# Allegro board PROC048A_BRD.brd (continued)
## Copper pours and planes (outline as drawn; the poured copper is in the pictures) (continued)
1V1 on TOP: 73.25,59.99 75.28,59.99 75.41,60.12 76.04,60.12 76.42,59.74 76.42,58.85 76.04,58.85 75.53,59.36 73.25,59.36 73.12,59.48 73.12,59.86
1V1 on TOP: 48.94,56.86 48.94,55.07 49.14,54.88 50.68,54.88 51.1,55.29 54.45,55.29 54.7,55.55 54.7,57.45 54.58,57.58 53.18,57.58 53.05,57.45 51.66,57.45 51.22,57.01 49.09,57.01
1V1 on BOTTOM: 72.38,63.53 72.61,63.29 72.61,61.9 72.93,61.57 74.19,61.57 74.39,61.77 76.42,61.77 76.55,61.64 76.55,58.97 76.42,58.85 75.66,58.85 75.53,58.97 75.53,59.23 75.41,59.36 73.39,59.36 72.43,58.39 72.43,53.21 70.57,51.35 60.55,51.35 59.53,52.37 59.53,57.32 59.4,57.45 56.48,57.45 56.23,57.2 56.23,56.18 55.85,55.8 49.75,55.8 49.24,56.31 49.24,67.73 50.31,68.79 63.59,68.79 63.92,68.47 63.92,65.13 65.52,63.53 ; 1 cut-out
1V35 on TOP: 36.42,66.59 36.42,63.8 36.16,63.55 32.48,63.55 32.29,63.74 32.29,66.53 32.48,66.72 36.29,66.72
1V35 on BOTTOM: 93.57,36.11 93.57,34.51 93.46,34.4 93.46,32.2 92.24,30.98 86.76,30.98 86.45,30.67 86.45,27.42 86.84,27.03 93.6,27.03 93.97,26.66 95.32,26.66 95.4,26.74 95.4,30.83 95.39,30.84 95.39,31.56 95.09,31.86 95.09,34.72 94.84,34.97 94.33,34.97 94.07,35.23 94.07,36.11 93.95,36.24 93.69,36.24
1V35 on L05_PWR1: 47.08,31.29 47.08,36.5 48.12,37.53 48.12,45.04 46.82,46.33 33.59,46.33 32.61,47.31 32.61,53.85 30.97,55.49 30.97,67.86 31.73,68.62 47.97,68.62 53.61,74.26 99.55,74.26 100.81,73 100.81,42.7 100.98,42.52 100.98,24.96 100.12,24.1 49.62,24.1 48.48,25.24 48.48,28.99 47.1,30.37 47.1,31.27
2V5 on TOP: 52.19,66.62 55.89,66.62 56.1,66.84 56.1,68.85 55.94,69.01 50.26,69.01 49.88,68.63 49.88,64.94 50,64.82 51.37,64.82 51.48,64.92 51.48,65.91
2V5 on TOP: 74.39,61.01 73.5,61.01 73.5,61.9 73.25,62.15 73.25,62.28 74.14,63.17 74.26,63.17 74.39,63.04
2V5 on TOP: 73.25,54.15 73.25,57.07 74.39,57.07 74.39,54.66 74.64,54.4 74.64,54.15 74.52,54.02 73.37,54.02
2V5 on BOTTOM: 30.88,50.92 34.36,50.92 34.77,51.33 34.74,53.51 34.45,53.8 30.92,53.8 30.68,53.56 30.68,51.13
2V5 on BOTTOM: 73.05,53.66 74.33,53.66 74.5,53.82 74.5,54.47 74.22,54.74 74.22,56.13 74.09,56.27 73.13,56.27 72.94,56.08 72.94,53.77
2V5 on L03_SIG1: 48.86,63.8 48.86,72 49.56,72.69 74.03,72.69 74.88,71.84 74.88,53.74 74.33,53.19 63.9,53.19 63.34,53.75 63.34,62.61 62.84,63.11 49.55,63.11
2V5 on L06_PWR2: 49.96,68.31 49.96,65.03 50.36,64.63 63.41,64.63 63.98,65.2 63.98,80.56 63.34,81.2 18.76,81.2 17.56,79.99 17.56,43.04 17.87,42.72 29.94,42.72 30.7,41.96 30.7,35.99 31.72,34.97 40.48,34.97 40.73,35.23 40.73,37.26 39.97,38.02 39.97,50.47 34.38,56.05 34.38,67.99 35.75,69.35 48.91,69.35
2V5_A on TOP (solid shape): 62.11,75.1 62.11,73.15 61.88,72.92 60.29,72.92 60.04,72.66 60.04,67.19 59.66,66.81 57.01,66.81 56.8,67.01 56.8,74.91 57.12,75.23 61.98,75.23
3V3 on TOP (solid shape): 91.45,24.66 91.39,24.5 91.23,24.44 90.11,24.62 90.23,25.66 91.27,25.78
3V3 on TOP: 46.83,63.55 43.02,63.55 42.89,63.67 42.89,66.47 43.15,66.72 46.83,66.72 47.08,66.47 47.08,63.8
3V3 on TOP: 82.39,10.59 82.64,10.33 83.53,10.33 83.66,10.46 83.66,11.6 83.53,11.73 82.64,11.73
3V3 on TOP: 89.69,81.3 89.69,79.99 89.86,79.82 91,79.82 91.19,80.01 91.19,81.27 91,81.47 89.85,81.47
3V3 on TOP: 90.06,83.76 91.08,83.76 91.27,83.94 91.27,85.25 91.1,85.42 90.06,85.42 89.87,85.23 89.87,83.95
3V3 on BOTTOM: 4.57,69.81 4.57,71.26 4.84,71.53 14.77,71.53 15,71.3 15,69.69 14.88,69.57 4.81,69.57
3V3 on BOTTOM: 2.28,91.84 2.13,91.99 2.13,93.01 2.28,93.16 19.28,93.16 19.28,93.17 20,93.17 20.12,93.05 20.12,92 19.96,91.84
3V3 on BOTTOM: 31.46,15.4 31.46,16.05 31.21,16.3 27.27,16.3 27.15,16.43 27.15,17.45 27.27,17.57 32.23,17.57 32.5,17.3 32.5,15.43 32.4,15.33 31.53,15.33
3V3 on L06_PWR2: 1.02,6.02 1.02,93.98 99.3,93.98 100.98,92.3 100.98,6.02
3V3_A on TOP (solid shape): 49.5,74.98 49.5,73.07 49.24,72.82 48.48,72.82 48.23,72.56 48.23,69.11 47.74,68.63 47.73,68.63 46.33,67.23 44.54,67.23 44.35,67.42 44.35,75.04 44.54,75.23 49.24,75.23
5V on TOP (solid shape): 54.58,83.36 54.58,82.95 54.48,82.77 54.45,82.58 54.45,81.1 54.58,80.97 54.58,80.18 55.06,79.7 55.89,79.7 56.23,79.36 56.23,74.29 56.13,74.19 53.36,74.19 53.05,74.5 53.05,79.93 52.42,80.56 52.42,81.18 52.42,81.18 52.42,82.58 52.39,82.77 52.29,82.95 52.29,83.36 52.42,83.49 54.45,83.49
5V on TOP (solid shape): 29.81,83.36 29.81,82.95 29.72,82.77 29.69,82.58 29.69,81.1 29.81,80.97 29.81,80.18 30.32,79.68 31.18,79.68 31.46,79.39 31.46,74.56 31.33,74.43 28.46,74.43 28.42,74.48 28.42,79.89 28.2,80.11 28.2,80.12 28.18,80.12 27.65,80.65 27.65,81.18 27.65,82.58 27.62,82.77 27.53,82.95 27.53,83.36 27.65,83.49 29.69,83.49
5V on BOTTOM: 46.63,57.38 47.72,58.47 47.72,68.2 48.91,69.39 56.36,69.39 57.5,70.53 57.5,92.88 56.61,93.77 38.07,93.77 37.81,93.52 37.81,92.38 37.43,91.99 35.27,91.99 34.89,92.38 34.89,93.65 34.77,93.77 25.62,93.77 24.61,92.76 24.61,90.22 24.1,89.71 19.04,89.71 18.45,89.11 18.45,58.2 19.27,57.38
GND on TOP (solid shape): 52.55,79.68 52.55,74.21 53.18,73.58 55.09,73.58 55.21,73.45 55.21,69.9 54.9,69.58 50.58,69.58 50.25,69.9 50.25,77.43 50.26,77.43 50.26,79.55 50.49,79.77 52.45,79.77
GND on TOP (solid shape): 27.91,79.68 27.91,74.21 28.11,74.01 28.17,74.01 28.25,73.92 30.23,73.92 30.32,73.83 30.32,69.77 29.94,69.39 26.26,69.39 26.25,69.39 25.77,69.39 25.49,69.66 25.49,77.5 25.5,77.5 25.5,79.55 25.8,79.86 27.12,79.86 27.13,79.87 27.72,79.87
GND on TOP: 10.93,35.65 10.93,37.59 11.06,37.72 11.88,37.72 12.04,37.88 12.04,39.41 11.91,39.54 9.62,39.54 9.39,39.31 9.39,35.64 9.59,35.44 10.72,35.44
GND on TOP: 79.6,11.73 80.23,11.73 80.61,11.35 81.76,11.35 81.88,11.22 81.88,9.7 81.76,9.57 79.72,9.57 79.47,9.83 79.47,11.6
GND on TOP: 17.39,68.62 15.85,68.62 15.69,68.78 15.69,73.72 15.86,73.89 17.46,73.89 17.76,73.59 17.76,68.99
GND on TOP: 94.9,75.68 94.71,75.48 93.95,75.48 93.57,75.87 93.57,76.88 93.82,77.14 94.71,77.14 94.9,76.94
GND on TOP: 62.89,73.12 62.32,72.56 62.32,69.9 62.07,69.64 60.95,69.64 60.79,69.49 60.79,68.33 60.88,68.25 67.73,68.25 68.42,68.94 68.42,70.51 68.14,70.79 65.1,70.79 64.84,71.04 64.84,72.9 64.62,73.12
GND on TOP: 95.22,28.49 95.22,27.1 95.09,26.97 94.07,26.97 93.95,27.1 93.95,28.49 94.07,28.62 95.09,28.62
GND on TOP: 54.67,54.82 54.88,54.62 54.88,54.09 53.38,52.59 50.8,52.59 50.69,52.7 50.69,54.15 51.15,54.61 53.42,54.61 53.63,54.82
GND on TOP: 25.63,39.16 25.52,39.26 25.05,39.26 24.98,39.2 24.98,35.61 25.12,35.48 25.37,35.48 25.63,35.74
GND on TOP: 47.79,67.68 48.8,67.68 49.12,67.36 49.12,64.56 49.38,64.3 53.32,64.3 53.56,64.05 53.56,62.96 53.4,62.8 49.09,62.8 48.1,61.81 48.1,60.24 47.97,60.12 46.07,60.12 45.81,59.86 45.81,57.97 45.69,57.84 41.99,57.84 41.52,58.31 41.52,62.66 41.89,63.04 47.08,63.04 47.59,63.56 47.59,67.48
GND on TOP: 38.07,74.09 38.07,68.88 38.19,68.75 42,68.75 42.13,68.88 42.13,74.09 42,74.21 38.19,74.21
GND on BOTTOM: 70.07,48.04 79.66,48.04 79.81,48.18 79.81,49.18 79.71,49.27 70.05,49.27 69.94,49.16 69.94,48.17
GND on BOTTOM: 87.51,33.53 87.97,33.53 88.15,33.35 92.45,33.35 92.58,33.23 92.58,32.05 92.31,31.78 87.39,31.78 87.28,31.89 87.28,33.31
GND on BOTTOM: 65.95,26.97 68.23,26.97 68.41,26.8 71.37,26.8 71.51,26.65 71.51,24.2 71.13,23.82 66.25,23.82 65.81,24.27 65.81,26.83
GND on BOTTOM: 25.37,78.79 26.64,78.79 26.89,78.53 26.89,76.75 27.65,75.99 27.65,75.61 27.4,75.36 25.37,75.36 24.99,75.74 24.99,78.41
GND on BOTTOM: 23.08,40.81 26.38,44.12 26.38,50.21 25,51.6 25,54.79 25.25,55.04 29.94,55.04 30.17,54.81 30.17,48.96 31.14,47.99 31.14,46.37 31.04,46.27 30.45,46.27 30.19,46.02 30.19,43.61 30.7,43.1 30.7,41.83 29.18,40.31 28.03,40.31 24.1,36.37 10.05,36.37 9.62,36.8 9.62,39.92 10.51,40.81
GND on BOTTOM: 42,41.19 42.39,41.19 43.78,39.8 43.78,39.04 43.66,38.91 43.02,38.91 43.02,38.65 42.64,38.27 42,38.27 41.88,38.15 41.88,37.77 42,37.64 42.77,37.64 42.77,37 42.64,36.88 39.21,36.88 39.18,36.85 37.66,36.85 37.58,36.93 37.58,37.28 37.72,37.42 38.19,37.42 38.3,37.53 38.3,38.23 38.39,38.32 38.83,38.32 38.87,38.28 38.87,37.55 38.94,37.48 39.9,37.48 39.97,37.56 39.97,38.65 39.21,39.42 39.21,45.13 39.72,45.64 41.24,45.64 41.37,45.51 41.37,42.59 41.62,42.34 41.62,41.58
GND on BOTTOM: 37.5,22.06 37.36,22.2 37.36,23.33 37.44,23.4 39.19,23.4 39.43,23.16 41.37,23.16 41.66,23.46 42.23,23.46 42.35,23.46 42.43,23.37 42.43,22.28 42.21,22.06
GND on BOTTOM: 61.36,89.95 61.01,90.3 61.01,93.1 61.25,93.34 63.27,93.34 63.53,93.07 63.53,90.3 63.19,89.95
GND on BOTTOM: 86.1,35.89 86.47,36.26 86.47,40.8 86.33,40.95 85.5,40.95 85.41,40.86 85.41,35.92 85.45,35.89
GND on BOTTOM: 95.6,32.08 95.6,34.72 98.01,34.72 98.46,35.17 98.46,37.24 98.32,37.38 95.6,37.38 95.34,37.13 95.34,37 94.93,36.59 91.49,36.59 91.28,36.8 91.28,38.02 91.37,38.1 94.7,38.1 94.97,38.38 94.97,39.16 95.42,39.61 100.37,39.61 100.73,39.25 100.73,32.15 100.31,31.73 95.95,31.73
GND on BOTTOM: 35.02,34.59 35.91,34.59 36.16,34.34 36.16,33.96 36.29,33.83 37.56,33.83 37.81,33.57 38.19,33.57 38.32,33.7 38.32,33.96 38.83,34.46 40.23,34.46 40.36,34.6 40.36,35.86 40.23,35.99 39.85,35.99 39.72,35.86 39.72,35.73 39.59,35.73 39.46,35.61 39.08,35.61 38.96,35.73 37.05,35.73 36.92,35.86 36.92,36.62 36.54,36.62 36.01,36.09 35.25,36.09 34.64,35.48 34.64,34.97 34.33,34.66 33.56,34.66 33.5,34.72 33.5,36.11 33.37,36.24 32.61,36.24 31.59,35.23 31.59,33.83 32.23,33.19 34.51,33.19 34.77,33.45 34.77,34.34
GND on BOTTOM: 84.16,32.59 84.26,32.49 84.26,30.99 84.01,30.73 82.34,30.73 82.18,30.58 80.34,30.58 80.09,30.83 80.09,32.47 80.21,32.59
GND on BOTTOM: 50.01,78.66 51.4,78.66 51.53,78.53 51.53,76.88 52.55,75.87 52.55,75.36 52.42,75.23 50.01,75.23 49.75,75.48 49.75,78.41
GND on L02_GND1, L07_GND3: 1.02,6.02 1.02,93.98 100.98,93.98 100.98,6.02
GND on L04_GND2: 1.02,6.02 1.02,93.98 100.98,93.98 100.98,6.02
GND on L05_PWR1: 1.02,76.88 1.02,93.98 100.98,93.98 100.98,75.48 53.43,75.48 47.59,69.64 34.77,69.64 28.8,75.61 2.29,75.61 ; 1 cut-out
GND on L05_PWR1: 1.02,6.02 1.02,23.03 100.98,23.03 100.98,6.02
GND on L09_GND4: 1.02,6.02 1.02,93.98 100.98,93.98 100.98,6.02
GND_EARTH on TOP: 90.52,68.12 91.28,68.12 91.66,67.74 94.84,67.74 94.96,67.61 94.96,66.34 94.84,66.21 90.52,66.21 90.26,66.47 90.26,67.86
GND_SDCD on BOTTOM: 64.18,93.79 64.38,93.98 67.96,93.98 68.23,93.72 68.23,90.97 67.8,90.55 64.54,90.55 64.18,90.9
GND_SDCD on L03_SIG1: 66.01,93.9 85.05,93.9 85.54,93.41 85.54,77.21 84.86,76.54 66.89,76.54 65.65,77.77 65.65,93.54
VCC5V_CONN on TOP: 20.92,35.1 20.92,35.99 21.81,36.88 21.81,37.94 20.89,38.86 18.04,38.86 17.01,37.84 17.01,36.02 16.48,35.48 14.7,35.48 14.57,35.35 12.67,35.35 12.54,35.48 12.54,39.8 12.29,40.05 7.97,40.05 6.57,41.45 1.69,41.45 1.02,42.12 1.02,51.01 1.88,51.86 6.31,51.86 7.22,50.95 7.22,47.68 9.26,45.64 23.84,45.64 24.48,45 24.48,35.61 24.35,35.48 23.72,35.48 23.21,34.97 21.05,34.97
VCC5V_EXT on TOP: 22.4,46.99 22.92,47.51 22.92,60.91 22.32,61.51 10.38,61.51 7.08,58.21 7.08,53.26 8.21,52.13 9.78,52.13 11.09,50.82 11.09,47.37 11.48,46.99
VCC_1V1 on TOP (solid shape): 24.93,75.29 24.93,73.14 24.35,72.56 24.35,67.74 23.97,67.36 20.29,67.36 19.91,67.74 19.91,75.36 20.03,75.48 24.73,75.48
VCC_AUX on BOTTOM: 35.23,49.45 35.23,44.1 34.69,43.56 31.04,43.56 30.73,43.87 30.73,45.6 30.81,45.67 31.7,45.67 31.82,45.79 31.82,48.4 31.31,48.9 31.31,49.7 31.58,49.97 34.71,49.97
VCC_AUX on L08_SIG2: 41.24,37.64 45.2,37.64 46.88,39.32 46.88,39.89 47.37,40.38 48.78,40.38 49.39,39.78 49.39,39.46 48.94,39 48.94,38.19 47.97,37.22 47.97,36.86 47.66,36.55 47.66,34.11 47.97,33.8 47.97,27.75 48.68,27.04 50.04,27.04 50.39,26.7 50.39,25.57 49.88,25.07 41.75,25.07 41.24,25.57 41.24,29.38 40.86,29.76 39.34,29.76 38.96,30.15 38.96,31.54 38.32,31.54 37.31,32.56 34.51,32.56 31.97,35.1 29.18,35.1 27.53,36.75 27.53,43.73 28.67,44.88 29.87,44.88 30.7,45.7 36.04,45.7 39.24,42.5 39.24,39.64
VCC_CORE on TOP: 24.61,66.47 24.61,63.8 24.35,63.55 20.67,63.55 20.41,63.8 20.41,66.47 20.67,66.72 24.35,66.72
VCC_CORE on BOTTOM: 40.86,36.24 40.86,34.35 40.67,34.16 40.32,34.16 40.32,33.5 40.48,33.33 40.48,32.94 39.59,32.05 39.21,32.05 39.08,32.18 39.08,32.56 38.83,32.81 37.81,32.81 37.31,33.32 36.67,33.32 36.42,33.07 36.42,32.18 36.8,31.8 36.8,30.27 36.92,30.15 37.56,30.15 37.81,29.89 38.45,29.89 38.96,30.4 38.96,30.65 39.21,30.91 45.69,30.91 46.07,31.29 46.07,33.07 46.32,33.32 46.32,34.59 46.07,34.84 46.07,36.5 45.94,36.62 41.24,36.62
VCC_CORE on L05_PWR1: 46.07,31.5 45.58,31.02 36.46,31.02 35.9,30.46 35.9,26.2 34.38,24.68 2.38,24.68 1.49,25.57 1.49,73.2 2.63,74.34 28.29,74.34 29.5,73.14 29.5,55.36 31.6,53.25 31.6,46.69 33.02,45.27 46.13,45.27 47.08,44.31 47.08,38.27 46.07,37.26
VCCHTX on TOP: 45.27,54.28 48.61,54.28 48.99,53.89 48.99,51.61 48.63,51.25 43.36,51.25 41.75,52.86 41.75,56.95 42.13,57.33 46.44,57.33 46.5,57.39 48.03,57.39 48.13,57.29 48.13,55.55 47.87,55.29 45.26,55.29 45.16,55.19 45.16,54.39
VCCHTX on BOTTOM: 39.39,23.93 39.64,23.68 40.18,23.68 40.3,23.8 40.3,24.59 40.44,24.73 40.44,25.36 40.35,25.45 37.99,25.45 37.3,24.75 37.3,24.05 37.42,23.93
VCCHTX on L03_SIG1: 37.58,24.84 37.94,25.19 38.07,25.19 38.83,25.95 38.83,29.64 39.34,30.15 39.34,36.5 39.79,36.95 42.96,36.95 43.47,37.45 43.47,38.09 43.94,38.55 44.43,38.55 45.09,39.21 45.09,39.99 46.07,40.97 46.07,42.09 46.33,42.35 46.33,44.75 46.76,45.18 46.76,55.71 47.07,56.03 55.44,56.03 56.07,55.4 56.07,48.12 54.24,46.29 54.24,43.89 50.72,40.37 50.72,37.65 50.51,37.44 48.96,37.44 48.16,36.65 48.16,25.96 48.96,25.17 48.96,23.29 48.68,23.01 37.8,23.01 37.58,23.23
VCCHTX_1V1 on TOP: 48.74,61.65 48.74,60.07 48.26,59.6 46.52,59.6 46.32,59.4 46.32,58.13 46.51,57.95 48.71,57.95 49.11,57.54 50.77,57.54 51.29,58.07 51.29,58.67 51.38,58.76 51.38,60.83 51.48,60.92 51.48,62.17 51.34,62.3 49.38,62.3
VCCHTX_C on BOTTOM: 41.05,25.19 40.82,24.96 40.82,23.81 40.88,23.75 41.24,23.75 41.46,23.96 43.95,23.96 44.04,24.05 44.04,24.94 43.78,25.19
VCCHTX_C on L05_PWR1: 47.08,28.95 46.25,29.78 37.79,29.78 37.31,29.3 37.31,24.56 38.07,23.8 46.2,23.8 47.08,24.68
(no net) on TOP: 22.58,86.28 25.75,86.28 26.13,85.9 26.13,84.16 26.56,83.73 26.56,82.19 26.41,82.04 25.92,82.04 25.15,82.81 22.61,82.81 22.32,83.1 22.32,86.02
(no net) on TOP: 26.26,69.39 29.94,69.39 30.32,69.77 30.32,73.83 30.15,74.01 28.11,74.01 27.91,74.21 27.91,79.8 27.84,79.87 25.81,79.87 25.49,79.55 25.49,69.66 25.77,69.39 26.25,69.39
(no net) on TOP: 50.25,69.9 50.58,69.58 54.9,69.58 55.21,69.9 55.21,73.45 55.09,73.58 53.18,73.58 52.55,74.21 52.55,79.68 52.45,79.77 50.49,79.77 50.25,79.54
(no net) on TOP: 55.72,81.96 56.36,81.96 57.18,82.78 58.84,82.78 59.02,82.96 59.02,86.14 58.89,86.27 56.51,86.27 55.97,85.73 55.97,83.99 55.47,83.49 55.47,82.22
(no net) on TOP: 49.75,77.64 49.75,79.93 50.11,80.29 51.7,80.29 51.86,80.45 51.86,81.13 51.47,81.52 50.38,81.52 49.6,82.3 47.08,82.3 46.6,81.81 46.6,79.95 46.07,79.42 44.16,79.42 44.04,79.29 44.04,77.52 44.16,77.39 49.5,77.39
(no net) on TOP: 27.4,83.23 27.4,81.58 27.65,81.33 27.65,80.65 28.42,79.89 28.42,74.48 28.46,74.43 31.33,74.43 31.46,74.56 31.46,79.39 31.18,79.68 30.32,79.68 29.81,80.18 29.81,83.36 29.69,83.49 27.65,83.49
(no net) on TOP: 30.96,81.96 31.59,81.96 32.41,82.78 34.08,82.78 34.26,82.96 34.26,86.14 34.12,86.27 31.45,86.27 31.21,86.03 31.21,83.99 30.7,83.49 30.7,82.22
(no net) on TOP: 57.12,75.23 61.98,75.23 62.11,75.1 62.11,73.15 61.88,72.92 60.29,72.92 60.04,72.66 60.04,67.19 59.66,66.81 57.01,66.81 56.8,67.01 56.8,74.91
(no net) on TOP: 20.8,82.05 20.8,79.93 19.78,78.91 19.78,77.64 19.91,77.52 24.79,77.52 24.99,77.71 24.99,79.84 25.52,80.36 26.9,80.36 27.09,80.55 27.09,81.13 26.7,81.52 25.62,81.52 24.84,82.3 21.04,82.3
(no net) on TOP: 56.98,79.35 56.15,80.18 55.34,80.18 55.09,80.44 55.09,81.33 55.21,81.45 56.61,81.45 57.43,82.28 59.47,82.28 59.91,81.83 59.91,79.93 60.17,79.68 62.2,79.68 62.45,79.42 62.45,77.64 62.07,77.26 57.37,77.26 56.99,77.64 56.99,79.04
(no net) on TOP: 32.1,75.48 37.05,75.48 37.43,75.1 37.43,73.45 36.42,72.44 36.42,67.99 35.78,67.36 32.35,67.36 31.97,67.74 31.97,75.36
(no net) on TOP: 52.16,83.23 52.16,81.58 52.42,81.33 52.42,80.56 53.05,79.93 53.05,74.5 53.36,74.19 56.13,74.19 56.23,74.29 56.23,79.36 55.89,79.7 55.06,79.7 54.58,80.18 54.58,83.36 54.45,83.49 52.42,83.49
(no net) on TOP: 47.35,86.28 50.51,86.28 50.89,85.9 50.89,84.16 51.3,83.76 51.3,82.16 51.18,82.04 50.69,82.04 49.92,82.81 47.38,82.81 47.08,83.1 47.08,86.02
(no net) on TOP: 30.57,80.18 30.32,80.44 30.32,81.33 30.45,81.45 31.84,81.45 32.67,82.28 34.71,82.28 35.15,81.83 35.15,79.93 35.4,79.68 37.43,79.68 37.69,79.42 37.69,77.9 37.31,77.52 32.35,77.52 32.23,77.64 32.23,79.7 31.74,80.18
(no net) on TOP: 24.35,67.74 24.35,72.56 24.93,73.14 24.93,75.29 24.73,75.48 20.03,75.48 19.91,75.36 19.91,67.74 20.29,67.36 23.97,67.36
(no net) on TOP: 48.23,69.11 48.23,72.56 48.48,72.82 49.24,72.82 49.5,73.07 49.5,74.98 49.24,75.23 44.54,75.23 44.35,75.04 44.35,67.42 44.54,67.23 46.33,67.23 47.73,68.63 47.74,68.63
BST1_REGA on TOP (solid shape): 35.15,81.83 35.15,79.93 35.4,79.68 37.43,79.68 37.69,79.42 37.69,77.9 37.31,77.52 32.35,77.52 32.23,77.64 32.23,79.7 31.74,80.18 30.57,80.18 30.32,80.44 30.32,81.33 30.45,81.45 31.84,81.45 32.67,82.28 34.71,82.28
BST1_REGB on TOP (solid shape): 59.91,81.83 59.91,79.93 60.17,79.68 62.2,79.68 62.45,79.42 62.45,77.64 62.07,77.26 57.37,77.26 56.99,77.64 56.99,79.04 56.98,79.35 56.15,80.18 56.12,80.18 56.1,80.21 55.31,80.21 55.09,80.44 55.09,81.33 55.21,81.45 56.61,81.45 57.43,82.28 59.47,82.28
BST2_REGA on TOP (solid shape): 25.62,81.52 26.7,81.52 27.09,81.13 27.09,80.55 26.9,80.36 25.52,80.36 24.99,79.84 24.99,77.71 24.79,77.52 19.91,77.52 19.78,77.64 19.78,78.91 20.8,79.93 20.8,82.05 21.04,82.3 24.84,82.3
BST2_REGB on TOP (solid shape): 50.38,81.52 51.47,81.52 51.86,81.13 51.86,80.45 51.7,80.29 50.11,80.29 49.75,79.93 49.75,77.64 49.5,77.39 44.16,77.39 44.04,77.52 44.04,79.29 44.16,79.42 46.07,79.42 46.6,79.95 46.6,81.81 47.08,82.3 49.6,82.3
DDR3_VDD on BOTTOM: 85.92,30.01 85.92,27.66 85.73,27.48 78.24,27.48 64.77,27.48 64.47,27.78 64.47,31.56 64.85,31.94 65.82,31.94 66.1,31.67 66.1,29.66 66.1,29.57 66.17,29.5 66.87,29.5 67.49,30.12 85.81,30.12
DDR3_VDD on L06_PWR2: 73.46,26.95 72.29,25.77 59.2,25.77 58.01,26.97 58.01,43.98 59.02,45 80.66,45 81.95,43.71 81.95,27.26 81.64,26.95
DDR3_VREF on BOTTOM: 89.07,38.83 91.65,38.83 91.83,39.01 91.83,40.31 91.69,40.45 90.31,40.45 90.11,40.65 90.11,41.48 89.96,41.64 88.91,41.64 88.84,41.57 88.84,39.06
DDR3_VTT on BOTTOM: 91.1,36.23 91.8,35.54 91.8,35.44 92.05,35.18 92.98,35.18 93.06,35.1 93.06,34.72 92.93,34.58 92.93,34.21 92.79,34.08 87.33,34.08 86.36,33.11 83.22,33.11 82.76,33.57 82.76,44.67 82.05,45.38 70.09,45.38 70.02,45.31 68.32,45.31 68.07,45.56 68.07,47.2 68.4,47.54 80.43,47.54 80.43,47.53 84.6,47.53 84.79,47.34 84.79,42.93 84.93,42.79 87.23,42.79 87.27,42.74 87.27,41.63 87.1,41.46 86.88,41.46 86.87,41.48 85.15,41.48 84.91,41.23 84.91,35.55 85.07,35.38 86.31,35.38 87.17,36.23 87.59,36.23 87.59,36.23
DDR_1V35 on TOP (solid shape): 37.43,75.1 37.43,73.45 36.42,72.44 36.42,67.99 35.78,67.36 32.35,67.36 31.97,67.74 31.97,75.36 32.1,75.48 37.05,75.48
ECP5U_VREF on BOTTOM: 90.04,45.22 90.04,44.34 90.07,44.31 90.07,43.16 90.22,43.01 91.51,43.01 91.59,43.1 91.59,43.91 91.68,44 91.99,44 92.09,44.11 92.09,45.23 91.92,45.4 90.21,45.4
ECP5U_VREF on BOTTOM: 52.67,23.03 52.93,23.29 52.93,24.94 52.76,25.11 50.58,25.11 50.24,25.45 50.24,26.98 49.98,27.24 49.16,27.24 48.77,27.63 48.77,28.4 48.77,29.22 48.77,29.22 48.88,29.33 50.16,29.33 50.27,29.44 50.27,31.06 50.14,31.19 48.08,31.19 47.92,31.02 47.92,29.65 46.78,28.52 46.78,25.8 47.22,25.37 47.97,25.37 48.23,25.11 48.23,23.54 48.74,23.03
ECP5U_VREF on L03_SIG1: 79.38,45.87 93.45,45.87 93.47,45.85 95.49,45.85 96.23,45.11 96.23,39.92 95.72,39.42 93.19,39.42 92.3,38.53 92.3,18.29 91.87,17.86 51.11,17.86 50.64,18.33 50.64,25.32 50.89,25.57 54.45,25.57 55.34,24.68 76,24.68 78.89,27.57 78.89,45.38
ECP5U_VREF on L06_PWR2: 45.17,31.02 45.17,25.82 47.06,23.92 53.05,23.92 53.43,24.3 53.43,26.08 52.93,26.59 49.5,26.59 48.74,27.35 48.74,30.78 48.23,31.29 45.43,31.29
FTDI1_VDD_1V8 on L05_PWR1: 63.59,6.27 62.62,7.25 62.62,15.62 64.19,17.19 78.2,17.19 80.49,14.91 80.49,7.89 78.87,6.27
FTDI2_VCORE on L05_PWR1: 71.98,87.68 91.28,87.68 92.42,86.53 92.42,75.8 91.89,75.26 72.71,75.26 71.34,76.63 71.34,87.04
FTDI_JTAG_TCK on TOP (solid shape): 91.09,21.85 90.32,20.8 90.26,20.77 90.21,20.8 89.44,21.85 90.26,22.47
FTDI_JTAG_TCK on L08_SIG2 (solid shape): 89.05,23.6 89.07,23.65 89.12,23.66 90.42,23.45 90.27,22.44 89.26,22.29
FTDI_JTAG_TDI on TOP (solid shape): 84.74,21.85 83.97,20.8 83.91,20.77 83.86,20.8 83.09,21.85 83.91,22.47
FTDI_JTAG_TDI on BOTTOM (solid shape): 83.93,22.46 84.07,21.45 82.79,21.24 82.73,21.26 82.71,21.32 82.91,22.61
FTDI_JTAG_TDO on TOP (solid shape): 85.88,23.58 85.9,23.64 85.96,23.66 87.25,23.45 87.1,22.44 86.09,22.29
FTDI_JTAG_TDO on TOP (solid shape): 87.91,21.85 87.15,20.8 87.09,20.77 87.03,20.8 86.27,21.85 87.09,22.47
FTDI_JTAG_TMS on TOP (solid shape): 80.76,25.62 80.14,24.8 79.09,25.57 79.06,25.62 79.09,25.68 80.14,26.45
FTDI_JTAG_TMS on L08_SIG2 (solid shape): 80.75,25.62 80.02,24.92 79.36,25.59 79.34,25.62 79.36,25.66 80.02,26.33
INITN on TOP (solid shape): 87.04,27.01 87.09,27.03 87.14,27.01 87.81,26.34 87.09,25.61 86.37,26.34
INITN on L08_SIG2 (solid shape): 87.1,25.62 86.37,24.92 85.71,25.59 85.69,25.62 85.71,25.66 86.37,26.33
MEM_VREF on BOTTOM: 87.28,43.99 87.22,43.93 87.22,43.37 87.14,43.29 86.1,43.29 86,43.39 86,44.98 86.36,45.34 86.36,46.33 86.54,46.51 87.15,46.51 87.28,46.38
MEM_VREF on L05_PWR1: 60.55,44.62 60.55,34.59 61.31,33.83 85.44,33.83 87.09,35.48 87.09,44.62 86.58,45.13 61.05,45.13
PROGRAMN on TOP (solid shape): 81.56,21.85 80.8,20.8 80.74,20.77 80.68,20.8 79.92,21.85 80.74,22.47
PROGRAMN on L08_SIG2 (solid shape): 80.75,22.46 80.9,21.45 79.59,21.24 79.54,21.25 79.53,21.3 79.74,22.61
N35698 on TOP: 90.19,65.66 90.19,64.16 88.74,62.71 88.74,50.1 90.09,48.76 90.09,46.73 88.99,45.64 86.2,45.64 85.69,46.15 85.69,67.74 86.2,68.25 89.38,68.25 89.5,68.12 89.5,66.35
N35954 on TOP (solid shape): 82.02,63.64 82.06,63.65 82.11,63.64 82.79,62.95 82.06,62.13 81.33,62.95
N15283211 on TOP (solid shape): 26.13,85.9 26.13,84.16 26.56,83.73 26.56,83.57 26.56,83.57 26.56,82.95 26.47,82.77 26.44,82.58 26.44,82.07 26.41,82.04 25.92,82.04 25.15,82.81 22.61,82.81 22.32,83.1 22.32,86.02 22.58,86.28 25.75,86.28
N15283215 on TOP (solid shape): 34.26,86.14 34.26,82.96 34.08,82.78 32.41,82.78 31.59,81.96 30.96,81.96 30.9,82.01 30.9,82.58 30.87,82.77 30.78,82.95 30.78,83.56 31.21,83.99 31.21,86.03 31.45,86.27 34.12,86.27
N15294700 on TOP (solid shape): 59.02,86.14 59.02,82.96 58.84,82.78 57.18,82.78 56.36,81.96 55.72,81.96 55.67,82.01 55.67,82.58 55.64,82.77 55.54,82.95 55.54,83.56 55.97,83.99 55.97,85.73 56.51,86.27 58.89,86.27
N15294712 on TOP (solid shape): 50.89,85.9 50.89,84.16 51.3,83.76 51.3,82.91 51.23,82.75 51.2,82.58 51.2,82.07 51.18,82.04 50.69,82.04 49.92,82.81 47.38,82.81 47.08,83.1 47.08,86.02 47.35,86.28 50.51,86.28
N15354055 on BOTTOM: 87.73,42.61 87.73,43.81 87.8,43.88 89.5,43.88 89.56,43.82 89.56,42.21 89.4,42.06 88.8,42.06 88.8,42.05 88.75,42.05 88.53,41.83 87.86,41.83 87.71,41.98 87.71,42.6
N15385918 on TOP: 96.61,30.27 100.81,30.27 100.98,30.1 100.98,25.88 100.68,25.57 98.9,25.57 98.39,25.07 96.87,25.07 95.7,26.24 95.7,29.36
N15385918 on TOP: 96.36,17.83 96.23,17.95 96.23,21 96.61,21.38 98.77,21.38 99.41,20.75 100.98,20.75 100.98,18.08 100.73,17.83
N15385918 on BOTTOM, L03_SIG1, L08_SIG2: 96.36,17.7 95.98,18.08 95.98,29.64 96.61,30.27 100.93,30.27 100.98,30.22 100.98,18 100.68,17.7
N15394548 on TOP: 95.46,78.27 95.6,78.41 100.86,78.41 100.98,78.28 100.98,74.51 100.55,74.09 98.9,74.09 98.77,73.96 98.77,73.58 98.65,73.45 96.23,73.45 95.46,74.23
N15394548 on TOP: 97.19,70.4 98.6,70.4 98.75,70.26 98.75,69.47 98.96,69.26 100.8,69.26 100.93,69.13 100.93,65.58 100.55,65.2 97.25,65.2 97.04,65.41 97.04,70.25
N15394548 on BOTTOM: 95.34,78.52 95.73,78.91 100.68,78.91 100.93,78.66 100.93,65.58 100.42,65.07 95.47,65.07 95.34,65.2
N15394548 on L03_SIG1: 100.98,78.28 100.98,65.76 100.42,65.2 95.73,65.2 95.34,65.58 95.34,78.15 95.6,78.41 100.86,78.41
N15394548 on L08_SIG2: 95.34,78.52 95.73,78.91 100.68,78.91 100.93,78.66 100.93,65.45 100.55,65.07 95.47,65.07 95.34,65.2
N16279120 on BOTTOM: 24.31,56.65 24.31,44.45 21.94,42.08 11.19,42.08 10.94,42.34 10.94,45.69 12.43,47.18 15.72,47.18 17.08,48.55 17.08,56.16 17.67,56.75 24.21,56.75
N16279144 on BOTTOM: 6.51,51.72 11.24,51.72 11.61,51.35 11.61,47.89 9.75,46.02 9.75,42.08 9.44,41.78 5.07,41.78 4.55,42.31 4.55,46.79 6.12,48.36 6.12,51.33

Small or netless copper shapes (teardrops, artwork), in the pictures only: 520 on TOP, 242 on BOTTOM, 176 on L03_SIG1, 194 on L08_SIG2

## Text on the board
Ref Des/Assembly Bottom: ASSEMBLY BOTTOM
Ref Des/Silkscreen Bottom: GND | DDR3_RSTN | FPGA_DONE | FPGA_JTAG_TMS | FPGA_INITN | ETHERNET_JACK | 5V_INPUT | 5V | ETH_LED_SPEED | ETH_1V8 | PROGRAMN | SDCARD_SLOT | FPGA_JTAG_TDI | FPGA_JTAG_TDO | FPGA_JTAG_TCK | 3V3 | REV. A | PROC048 | DCA1000EVM | S/N: | FY180266000102 | not FCC approved for resale. | For evaluation only;
User.Comments: CR_1_2 | PROC048 | TEXAS INSTRUMENTS
Ref Des/Assembly Top: ASSEMBLY TOP
Ref Des/Silkscreen Top: 6 | 12BIT_ON | 14BIT_ON | 16BIT_ON | 16BIT_OFF | 12BIT_OFF | 14BIT_OFF | DATA_TRAN_PRG | USER_SW3 | SD_DETECT | USER_SW2 | SD_FULL | USER_SW1 | SPARE | HW_CONFIG | RAW_MODE | DDR_FULL | 1243_MODE | FPGA_ERR | SD_STORE | LVDS_CAPT | LVDS_PATH_ERR | HDR_ERR | EEPROM_RD_FAIL | FPGA_CFG0 | FPGA_CFG1 | FPGA_CFG2 | FPGA_PROGRAMN_LED | FPGA_INITN | FPGA_RST | FPGA_RST_SW | GND | 5V_LED | RADAR_FTDI | FPGA_JTAG | FPGA_PROGRAMN_SW | RADAR_5V_IN | SPARE_GPIO | LVDS_MODE_SEL | CAPTURE_START | SW_CONFIG | DATA_MODE | AR1642_MODE | ETH_STREAM | DMM_PLAYBACK | DC_JACK_5V_IN | VCC_CORE | 60_PIN_RADAR_CONN | 1V35 | 1V1 | 2V5 | FPGA_DONE_LED
User.5: 12. | 13. | 14. | 11. | MINIMUM TRACEWIDTH AND SPACEING:0.0035"/0.0039" | PCB SHALL BE Pb FREE & RoHS COMPLAINT. | ALL UNCONNECTED VIA'S SHALL BE SUPPRESSED IN ALL INTERNAL LAYERS. | FINISHED BOARD THICKNESS :0.063"+/-10% | V-GROOVE | DETAIL-A
User.6: RoHS EXEMPT | 1243/1443-EVM | CAUTION HOT SURFACE | PROC010 REV A | U10 | L5 | U1 | U2 | U12 | U11 | D3 | FB2 | FB1 | J1 | TP1 | TP2 | Y1 | P1 | SW1 | SW2 | U3 | U4 | P4 | P3 | P2 | DS2 | DS3 | DS1 | Q1 | DS4 | F1 | J2 | P5 | P6 | J3 | 1 | 3 | HD_CONN | GND | GPIO1 | NRST | SOP1 | SOP0 | SOP2 | 5V | NERR_OUT | 5V_IN | CAN_L | CAN_H | USB
User.10: PROC048 | TEXAS INSTRUMENTS
User.25: GROUND-PLANE-04 | 12
User.26: BOARD OUTLINE
User.28: INNER-SIGNAL-02 | 11
User.37: 06 | 05 | 02 | 03 | 04 | EDGE COUPLED STRIPLINE | EDGE COUPLED MICROSTRIP | L3/L8 | L1/L10 | 5.5 | 4.2 | 3.5 | 4 | - | 8 | 4.5 | 6 | 90 | 100 | 50 | L2/L9 | L2/L4,L7/L9
User.38: 0.005 | 0.0037 | 1oz. | L08 | L09 | POWER-PLANE-2 | GROUND-PLANE-2 | INNER-SIGNAL-2 | GROUND-PLANE-4
User.41: FIGURE | SIZE | 8.0 | 34.0 | 36.0 | 40.0 | 66.0 | 72.0 | 88.0 | 128.0 | 170.0 | 52.0x24.0 | 120.0x30.0 | 140.0x40.0 | 230.0x170.0 | DRILL CHART: TOP to BOTTOM | ALL UNITS ARE IN MILS | TOLERANCE | +3.0/-3.0 | PLATED | NON-PLATED | QTY | 1382 | 4 | 10 | 15 | 2 | 3 | 1
